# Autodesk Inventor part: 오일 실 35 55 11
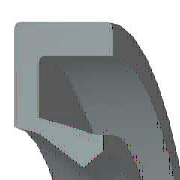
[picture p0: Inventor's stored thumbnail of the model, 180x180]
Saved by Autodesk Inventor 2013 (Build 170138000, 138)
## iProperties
IsCustomPart: 1
Created: 2012-02
Part Number: 오일 실 35 55 11
Material: 고무
Description: 오일 실 - 비스프링, 조립 GA
Document SubType Name: Modeling
Standard: JIS B 2402
Designer: mdu-01
Standards Organization: JIS
Language: ko-KR
Size Designation: 35 55 11 A
Categories: <MemberInstance><Categories><Category DisplayName="샤프트 부품" InternalName="7f7aeb1f-a693-4053-b835-cee3144e0d98" Mnemonic="SHFT"><Category DisplayName="실링" Intern
Density: 0.93 g/cm^3
Author: mdu-01
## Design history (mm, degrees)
body "Solid1"
revolve "회전1" stored, may be unused: angle "d27" = 360 deg
fillet "모깎기1" dims "d28" = 0.55 (= 0.05 x b)
sketch "스케치2"
  geometry: L1 (20.786, -8.25)-(21.786, -11); L2 (19.452, -7.563)-(20.786, -8.25); L3 (17.5, -3.025)-(19.452, -7.563); L4 (19.038, -1.65)-(17.5, -3.025); L5 (23.5, -9.625)-(19.038, -1.65); L6 (23.5, -0.55)-(23.5, -9.625); L7 (25.5, -0.55)-(23.5, -0.55); L8 (25.5, 0)-(25.5, -0.55); L9 (27.5, 0)-(25.5, 0); L10 (27.5, -11)-(27.5, 0); L11 (21.786, -11)-(27.5, -11); L12 (0, -9.6)-(0, 1.6) reference; L13 (28, 0)-(14, 0) reference
  constraints: 22 end point, 3 horizontal, 3 vertical
  dimensions: "d2" = 11 distance of L10.start L9.start (= b); "d4" = 2 distance of L9.start L8.start (= 0.1 x dd - 0.1 x Diam); "d6" = 0.55 distance of L8.start L7.start (= 0.05 x b); "d8" = 1.53846 horizontal distance of L4.start L3.start (= 0.0769231 x dd - 0.0769231 x Diam); "d10" = 1.375 vertical distance of L5.start L10.start (= 0.125 x b); "d12" = 2 distance of L7.start L6.start (= 0.1 x dd - 0.1 x Diam); "d14" = 1.1 vertical distance of L4.start L6.start (= 0.1 x b); "d16" = 5.71429 distance of L1.end L10.start (= 0.285714 x dd - 0.285714 x Diam); "d18" = 1 horizontal distance of L1.start L1.end (= 0.05 x dd - 0.05 x Diam); "d20" = 1.375 vertical distance of L4.start L3.start (= 0.125 x b); "d22" = 2.75 vertical distance of L1.start L1.end (= 0.25 x b); "d24" = 1.33333 horizontal distance of L2.start L1.start (= 0.0666667 x dd - 0.0666667 x Diam); "d26" = 0.6875 vertical distance of L2.start L1.start (= 0.0625 x b); "d29" = 0 distance between parallel lines of L13 L9; "d30" = 17.5 distance from line of L3.start L12 (= 0.5 x Diam); "d31" = 27.5 distance between parallel lines of L12 L10 (= 0.5 x dd)
other parameters: "dd" = 55 [user parameter; used in 7 equation terms], "Diam" = 35 [user parameter; used in 7 equation terms], "b" = 11 [user parameter; used in 8 equation terms], "d1" = 8 (derived), "d3" = 2 (derived), "d5" = 0.4 (derived), "d7" = 1.53846 (derived), "d9" = 1 (derived), "d11" = 2 (derived), "d13" = 0.8 (derived), "d15" = 5.71429 (derived), "d17" = 1 (derived), "d19" = 1 (derived), "d21" = 2 (derived), "d23" = 1.33333 (derived), "d25" = 0.5 (derived), "d32" = 0
